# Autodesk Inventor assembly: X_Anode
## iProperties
Shininess: 64.0
Length Units: 11269
Angle Units: 11279
Time Units: 11290
Mass Units: 11283
Length Display Precision: 3
Angle Display Precision: 2
Compacted: True
Created: 2003-02
Part Number: X_Anode
Document SubType Name: Assembly
Designer: hofer_a
Density: 0.0
Volumn: 0.0
Area: 0.0
PropertySet Name: Model Information
Control State: 0
Master: False
Checked Out: False
Author: hofer_a
